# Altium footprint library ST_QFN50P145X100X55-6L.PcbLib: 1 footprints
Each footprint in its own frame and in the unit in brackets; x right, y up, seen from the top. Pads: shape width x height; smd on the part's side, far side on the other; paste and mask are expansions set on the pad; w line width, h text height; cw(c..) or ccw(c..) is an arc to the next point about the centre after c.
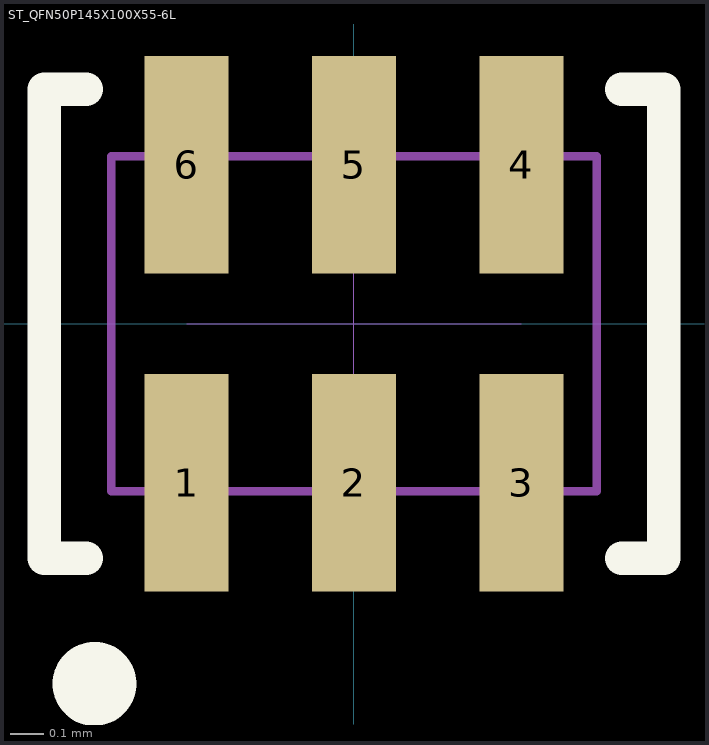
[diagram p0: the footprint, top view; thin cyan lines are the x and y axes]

## ST_QFN50P145X100X55-6L [mm] "ST_QFN50P145X100X55-6L"
pads (6):
  rect 0.25x0.65 smd paste-20 mask+0.025: 1(-0.5,-0.475) 2(0,-0.475) 3(0.5,-0.475) 4(0.5,0.475) 5(0,0.475) 6(-0.5,0.475)
Top Overlay:
  circle w0.2: c-0.775,-1.075 r0.025
  lines w0.1: -0.8,-0.7 -0.925,-0.7 -0.925,0.7 -0.8,0.7 ; 0.8,-0.7 0.925,-0.7 0.925,0.7 0.8,0.7
Top Paste:
  rectangle: 0.382,-0.785 0.618,-0.165
  rectangle: -0.118,-0.785 0.118,-0.165
  rectangle: -0.618,-0.785 -0.382,-0.165
  rectangle: 0.382,0.165 0.618,0.785
  rectangle: -0.118,0.165 0.118,0.785
  rectangle: -0.618,0.165 -0.382,0.785
Mechanical 5:
  text "2" at -0.03,-1 h0.05
  text "5" at -0.055,0.94 h0.05
  text "3" at 0.47,-1 h0.05
  text "4" at 0.445,0.94 h0.05
  text "1" at -0.53,-1 h0.05
  text "6" at -0.555,0.94 h0.05
Mechanical 6:
  lines w0.025: -0.725,-0.5 0.725,-0.5 0.725,0.5 -0.725,0.5 -0.725,-0.5
Mechanical 7:
  lines w0.025: -0.725,-0.5 -0.725,0.5 0.725,0.5 0.725,-0.5 -0.725,-0.5
Mechanical 15:
  lines w0.001: -0.5,0 0.5,0 ; 0,-0.5 0,0.5
3D body: height 0.6, standoff 0, extent -0.725,-0.5 0.725,0.5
